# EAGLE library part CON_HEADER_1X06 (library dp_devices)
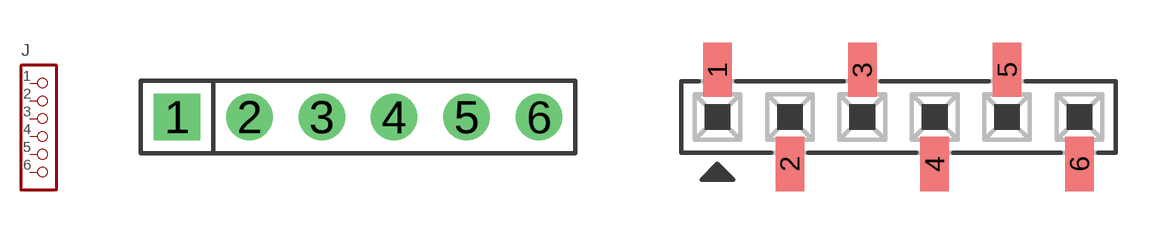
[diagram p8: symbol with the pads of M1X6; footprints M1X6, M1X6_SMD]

Designator prefix J

## CON_HEADER_1X06-PTH  [M1X6]
1  1
2  2
3  3  pas
4  4  pas
5  5  pas
6  6  pas

## CON_HEADER_1X06-SMD  [M1X6_SMD]
Pads as for M1X6

## CON_HEADER_1X06-PTH-RIGHT-ANGLED  [M1X6_MALE_RIGHT_ANGLED]
Pads as for M1X6

## CON_HEADER_1X06-SMD-RIGHT-ANGLED  [M1X6_MALE_RIGHT_ANGLED_SMD]
Pads as for M1X6

## Footprint M1X6 (pad centres in mm)
drill 1.02 pad 1.632 square: 1 0,0
drill 1.02 pad 1.632 round: 2 2.54,0; 3 5.08,0; 4 7.62,0; 5 10.16,0; 6 12.7,0

## Footprint M1X6_SMD (pad centres in mm)
1x06 0.1" header SMD, 1.00 x 1.90 pad size Mfr no: NPTC061KFXC-RC NPTC061KFXC-RC
smd 1 x 1.9: 1 -6.35,1.65; 2 -3.81,-1.65; 3 -1.27,1.65; 4 1.27,-1.65; 5 3.81,1.65; 6 6.35,-1.65

## Footprint M1X6_MALE_RIGHT_ANGLED (pad centres in mm)
1x06 Right angled male header PTH Mfr no: 22-28-8060 22-28-8060
drill 1.02 pad 1.632 square: 1 -6.35,-2.925
drill 1.02 pad 1.632 round: 2 -3.81,-2.925; 3 -1.27,-2.925; 4 1.27,-2.925; 5 3.81,-2.925; 6 6.35,-2.925

## Footprint M1X6_MALE_RIGHT_ANGLED_SMD (pad centres in mm)
1x06 Right angled male header SMD Mfr no: 961106-5500 961106-5500
smd 1.3 x 2.8: 1 -6.35,-3.3; 2 -3.81,-3.3; 3 -1.27,-3.3; 4 1.27,-3.3; 5 3.81,-3.3; 6 6.35,-3.3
